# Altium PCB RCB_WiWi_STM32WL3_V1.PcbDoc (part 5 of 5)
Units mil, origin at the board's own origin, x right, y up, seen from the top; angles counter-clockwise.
Board outline 1250.1 x 2647.64 mil, 10 copper layers (L01-TOP, L02-GND, L03-SIG, L04-GND, L05-PWR, L06-PWR, L07-GND, L08-SIG, L09-GND, L10-BOT), stack 62.1 mil thick; 342 components, 203 nets, 969 pads, 708 vias.
Unrouted connection lines stored in the file: 108.
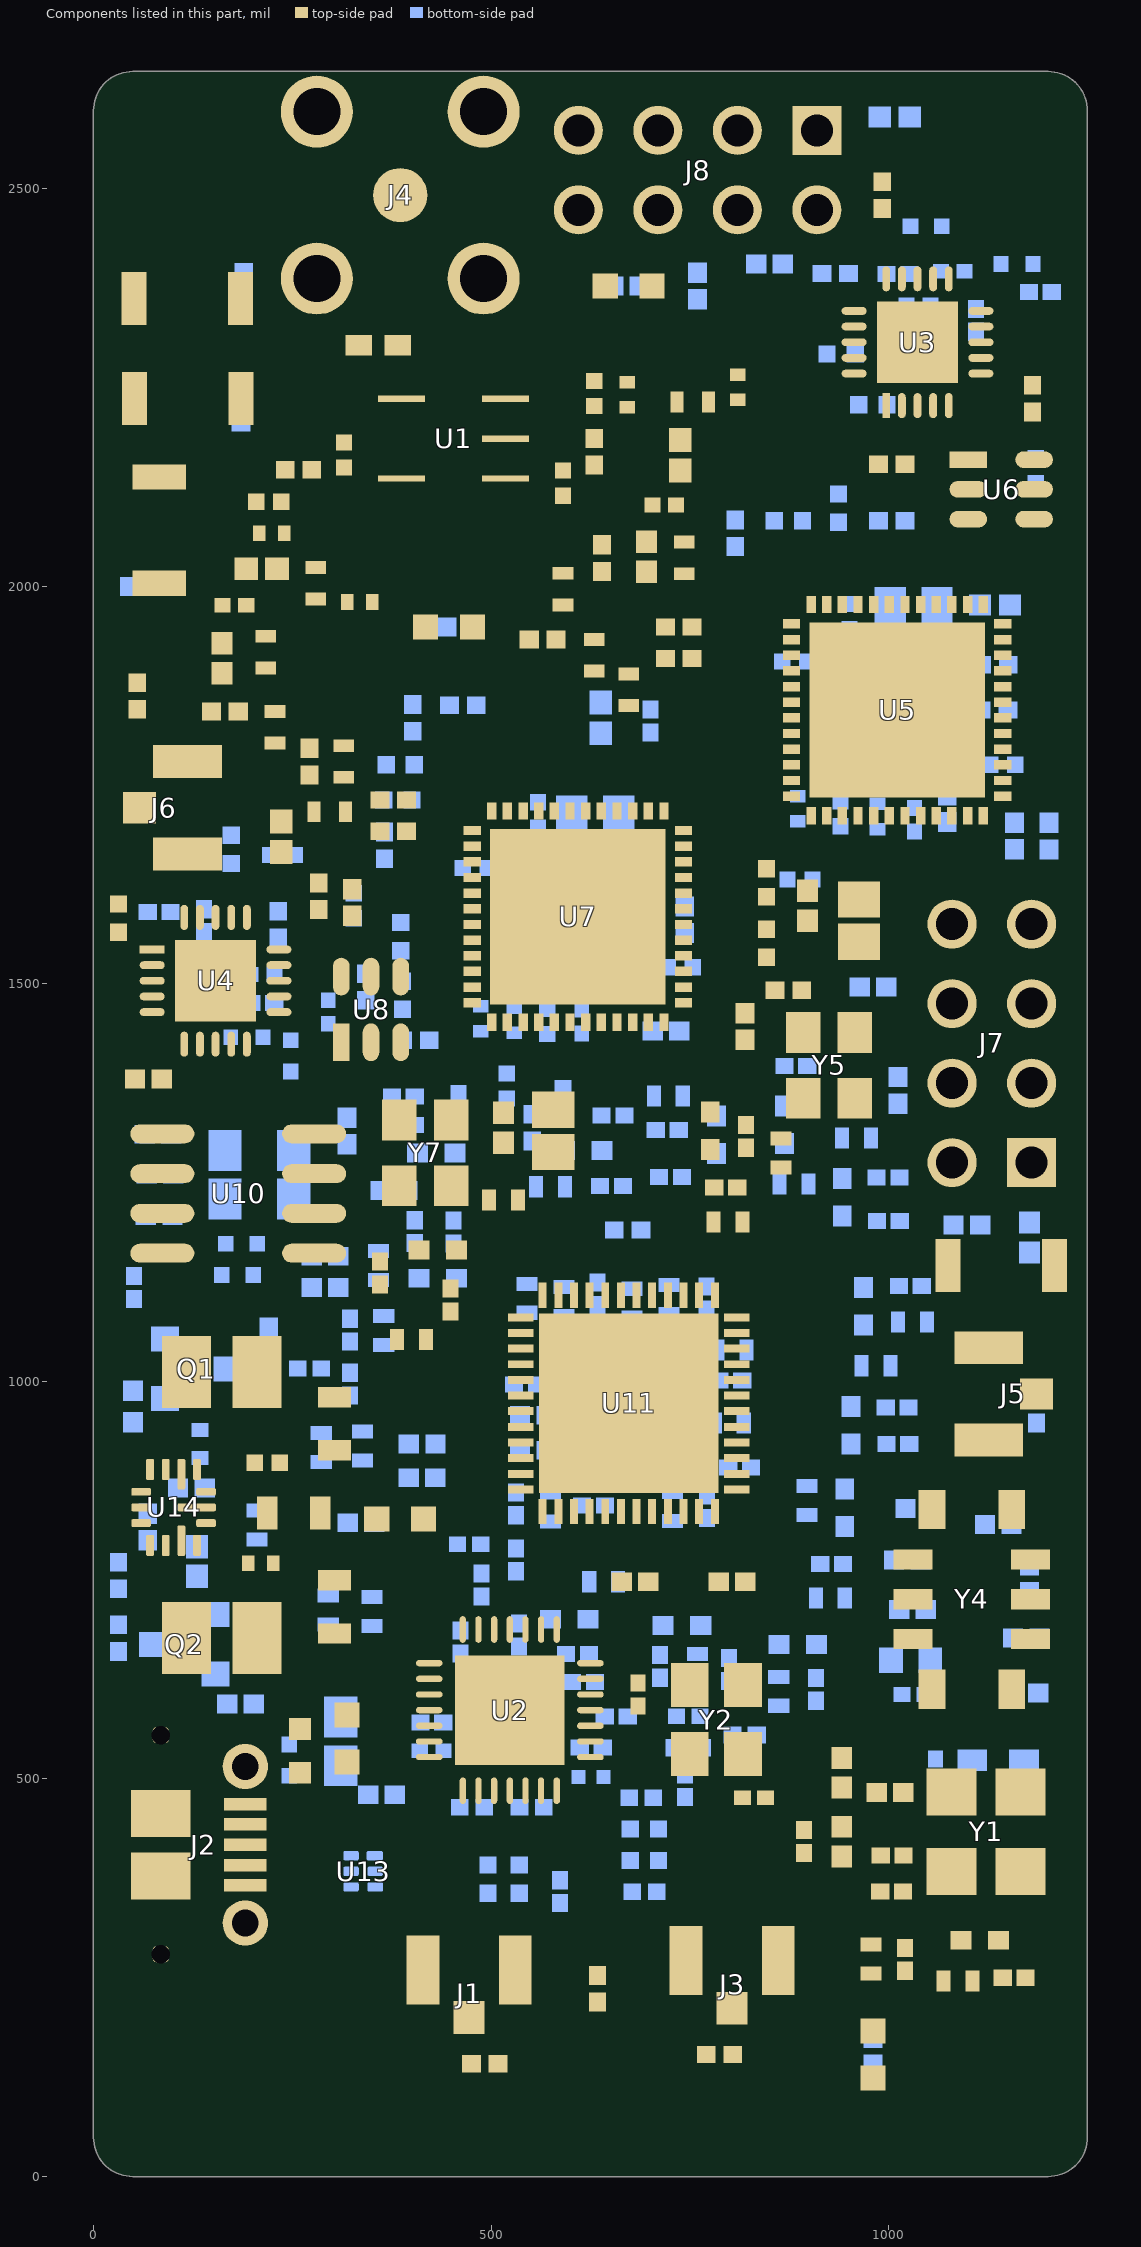
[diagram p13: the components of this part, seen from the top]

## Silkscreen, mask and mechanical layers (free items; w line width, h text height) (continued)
Board Shape:
  circle w10: c1136.81,2514.76 r61.02
  circle w10: c113.19,2514.76 r61.02
  circle w10: c113.19,132.87 r61.02
  circle w10: c1136.81,132.87 r61.02
  lines w10: 1200.69,2647.64 cw(c1200.69,2598.33) 1250,2598.33 1250,49.31 ; 1200.79,2647.64 49.31,2647.64 ccw(c49.31,2598.33) 0,2598.33 0,49.31 ccw(c49.31,49.31) 49.31,0 1200.79,0 ccw(c1200.79,49.31) 1250.1,49.31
